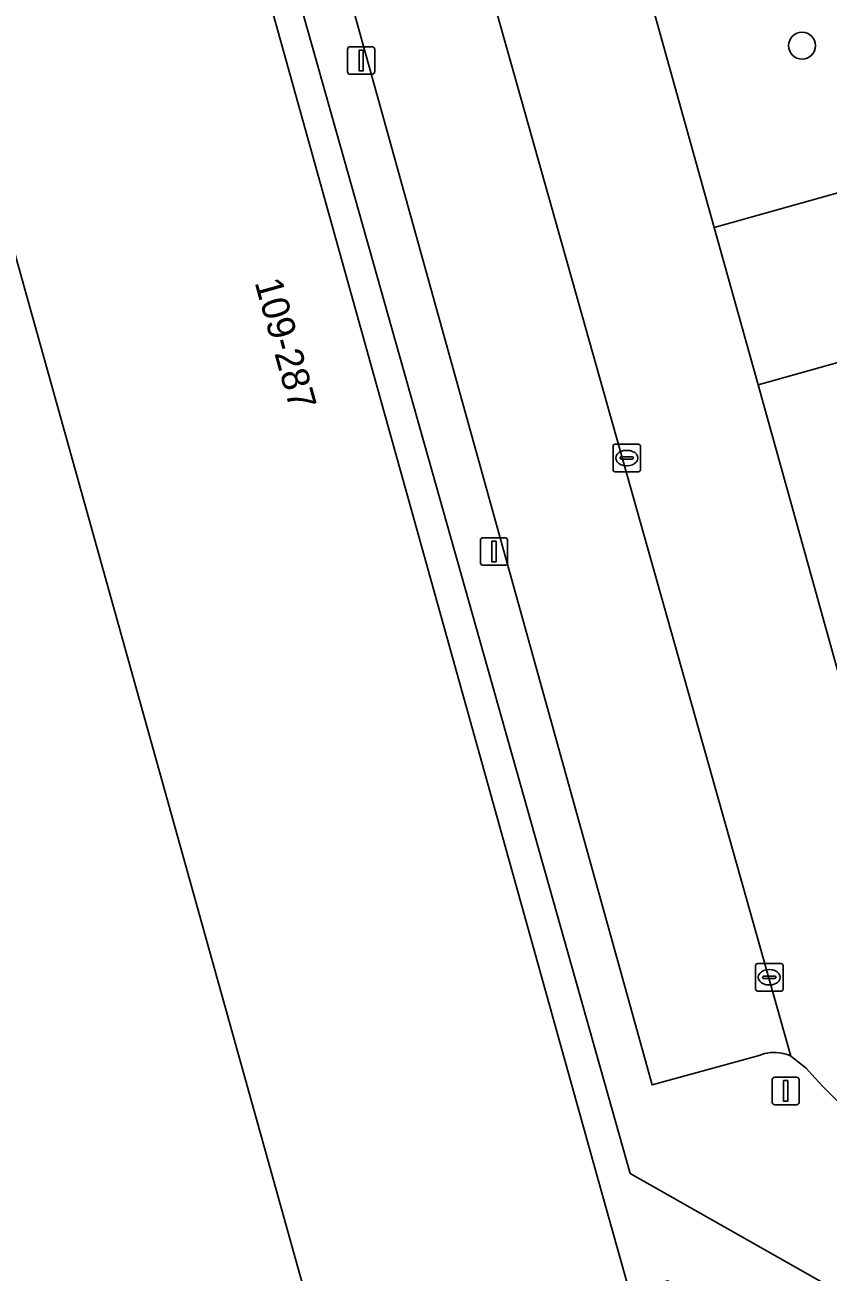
# Model space of a CAD drawing. Extents: x 159680 to 160786, y 387323 to 388340.
# Drawn here: x 159790.84 to 159820.07, y 387875.53 to 387920.9 of the extents above; entities that cross this region are included whole.
import ezdxf

# ---------------------------------------------------------------- set-up
doc = ezdxf.new("R2010")
doc.units = 0
for name, color, linetype in [('IMGEO_Boom', 7, 'Continuous'), ('IMGEO_Erf', 7, 'Continuous'), ('IMGEO_Kolk', 7, 'Continuous'), ('IMGEO_Lichtmast', 7, 'Continuous'), ('IMGEO_Pand', 7, 'Continuous'), ('IMGEO_Pand_nummerreeks', 7, 'Continuous'), ('IMGEO_Parkeervlak_open', 7, 'Continuous'), ('IMGEO_Rijbaan_lokaal_open', 7, 'Continuous'), ('IMGEO_Voetpad_open', 7, 'Continuous')]:
    doc.layers.add(name, color=color, linetype=linetype)

msp = doc.modelspace()

# ---------------------------------------------------------------- linework, layer by layer
at = {"layer": 'IMGEO_Boom'}
msp.add_circle((159819.119, 387920.147), 0.489, dxfattribs=at)
at = {"layer": 'IMGEO_Erf'}
msp.add_lwpolyline([(159855.695, 387800.602), (159856.484, 387800.91), (159853.031, 387810.594), (159849.48, 387809.209), (159834.729, 387847.038), (159833.556, 387846.581), (159832.044, 387847.281), (159828.131, 387857.251), (159823.313, 387869.646), (159817.654, 387873.188), (159815.606, 387870.293), (159814.209, 387869.903), (159816.632, 387861.214), (159809.352, 387859.172), (159805.677, 387858.141), (159779.046, 387953.498)], dxfattribs=at)
at = {"layer": 'IMGEO_Kolk'}
for p, q in [((159812.24, 387904.716), (159812.24, 387905.568)), ((159812.315, 387905.642), (159813.167, 387905.642)), ((159812.728, 387905.422), (159812.753, 387905.422)), ((159813.241, 387905.568), (159813.241, 387904.716)), ((159812.499, 387905.136), (159812.499, 387905.148)), ((159812.937, 387905.099), (159812.539, 387905.099)), ((159812.542, 387905.185), (159812.94, 387905.185)), ((159812.983, 387905.148), (159812.983, 387905.136)), ((159813.167, 387904.642), (159812.315, 387904.642)), ((159812.751, 387904.862), (159812.726, 387904.862)), ((159817.426, 387885.825), (159817.426, 387886.677)), ((159817.501, 387886.751), (159818.353, 387886.751)), ((159817.914, 387886.531), (159817.939, 387886.531)), ((159818.427, 387886.677), (159818.427, 387885.825)), ((159817.685, 387886.245), (159817.685, 387886.257)), ((159818.123, 387886.208), (159817.725, 387886.208)), ((159817.728, 387886.294), (159818.126, 387886.294)), ((159817.937, 387885.971), (159817.912, 387885.971)), ((159818.169, 387886.257), (159818.169, 387886.245)), ((159818.353, 387885.751), (159817.501, 387885.751))]:
    msp.add_line(p, q, dxfattribs=at)
for points in [[(159812.24, 387904.716), (159812.24, 387905.568)], [(159812.315, 387905.642), (159813.167, 387905.642)], [(159813.241, 387905.568), (159813.241, 387904.716)], [(159813.167, 387904.642), (159812.315, 387904.642)], [(159817.426, 387885.825), (159817.426, 387886.677)], [(159817.501, 387886.751), (159818.353, 387886.751)], [(159818.427, 387886.677), (159818.427, 387885.825)], [(159818.353, 387885.751), (159817.501, 387885.751)]]:
    msp.add_lwpolyline(points, dxfattribs=at)
for centre, radius, start, end in [((159812.317, 387905.566), 0.0765, 91.552, 178.448), ((159812.317, 387905.566), 0.0765, 91.552, 178.448), ((159813.165, 387905.566), 0.0765, 1.552, 88.448), ((159813.165, 387905.566), 0.0765, 1.552, 88.448), ((159812.539, 387905.145), 0.0403, 85.8775, 175.7526), ((159812.536, 387905.135), 0.0366, 178.938, 274.7102), ((159812.94, 387905.142), 0.043, 264.8664, 352.4533), ((159812.944, 387905.147), 0.0386, 1.7309, 96.639), ((159812.317, 387904.718), 0.0765, 181.552, 268.448), ((159812.317, 387904.718), 0.0765, 181.552, 268.448), ((159813.165, 387904.718), 0.0765, 271.552, 358.448), ((159813.165, 387904.718), 0.0765, 271.552, 358.448), ((159817.503, 387886.675), 0.0765, 91.552, 178.448), ((159817.503, 387886.675), 0.0765, 91.552, 178.448), ((159818.351, 387886.675), 0.0765, 1.552, 88.448), ((159818.351, 387886.675), 0.0765, 1.552, 88.448), ((159817.725, 387886.254), 0.0403, 85.8775, 175.7526), ((159817.722, 387886.244), 0.0366, 178.938, 274.7102), ((159818.126, 387886.251), 0.043, 264.8664, 352.4533), ((159818.13, 387886.256), 0.0386, 1.7309, 96.639), ((159817.503, 387885.827), 0.0765, 181.552, 268.448), ((159817.503, 387885.827), 0.0765, 181.552, 268.448), ((159818.351, 387885.827), 0.0765, 271.552, 358.448), ((159818.351, 387885.827), 0.0765, 271.552, 358.448)]:
    msp.add_arc(centre, radius, start, end, dxfattribs=at)
for centre, major_axis, ratio, start_param, end_param in [((159812.727, 387905.142), (-0.387, 0.002), 0.722429, 4.712389, 7.853982), ((159812.752, 387905.142), (-0.39, 0.002), 0.717154, 1.570796, 4.712389), ((159817.913, 387886.251), (-0.387, 0.002), 0.722429, 4.712389, 7.853982), ((159817.938, 387886.251), (-0.39, 0.002), 0.717154, 1.570796, 4.712389)]:
    msp.add_ellipse(centre, major_axis=major_axis, ratio=ratio, start_param=start_param, end_param=end_param, dxfattribs=at)
at = {"layer": 'IMGEO_Lichtmast'}
for p, q in [((159802.579, 387919.208), (159802.579, 387920.008)), ((159802.579, 387920.008), (159802.579, 387919.208)), ((159802.679, 387920.108), (159803.469, 387920.108)), ((159803.469, 387920.108), (159802.679, 387920.108)), ((159803.569, 387920.008), (159803.569, 387919.208)), ((159803.569, 387919.208), (159803.569, 387920.008)), ((159803.469, 387919.108), (159802.679, 387919.108)), ((159802.679, 387919.108), (159803.469, 387919.108)), ((159807.514, 387902.243), (159808.304, 387902.243)), ((159808.304, 387902.243), (159807.514, 387902.243)), ((159807.414, 387901.343), (159807.414, 387902.143)), ((159807.414, 387902.143), (159807.414, 387901.343)), ((159808.404, 387902.143), (159808.404, 387901.343)), ((159808.404, 387901.343), (159808.404, 387902.143)), ((159808.304, 387901.243), (159807.514, 387901.243)), ((159807.514, 387901.243), (159808.304, 387901.243)), ((159818.026, 387881.714), (159818.026, 387882.514)), ((159818.026, 387882.514), (159818.026, 387881.714)), ((159818.126, 387882.614), (159818.916, 387882.614)), ((159818.916, 387882.614), (159818.126, 387882.614)), ((159819.016, 387882.514), (159819.016, 387881.714)), ((159819.016, 387881.714), (159819.016, 387882.514)), ((159818.916, 387881.614), (159818.126, 387881.614)), ((159818.126, 387881.614), (159818.916, 387881.614))]:
    msp.add_line(p, q, dxfattribs=at)
for points in [[(159802.999, 387919.983), (159803.149, 387919.983), (159803.149, 387919.233), (159802.999, 387919.233), (159802.999, 387919.983)], [(159807.834, 387902.118), (159807.984, 387902.118), (159807.984, 387901.368), (159807.834, 387901.368), (159807.834, 387902.118)], [(159818.446, 387882.489), (159818.596, 387882.489), (159818.596, 387881.739), (159818.446, 387881.739), (159818.446, 387882.489)]]:
    msp.add_lwpolyline(points, dxfattribs=at)
for centre, start, end in [((159802.679, 387920.008), 90, 180), ((159802.679, 387920.008), 90, 180), ((159803.469, 387920.008), 0, 90), ((159803.469, 387920.008), 360, 90), ((159802.679, 387919.208), 180, 270), ((159802.679, 387919.208), 180, 270), ((159803.469, 387919.208), 270, 0), ((159803.469, 387919.208), 270, 0), ((159807.514, 387902.143), 90, 180), ((159807.514, 387902.143), 90, 180), ((159808.304, 387902.143), 0, 90), ((159808.304, 387902.143), 360, 90), ((159807.514, 387901.343), 180, 270), ((159807.514, 387901.343), 180, 270), ((159808.304, 387901.343), 270, 0), ((159808.304, 387901.343), 270, 0), ((159818.126, 387882.514), 90, 180), ((159818.126, 387882.514), 90, 180), ((159818.916, 387882.514), 0, 90), ((159818.916, 387882.514), 360, 90), ((159818.126, 387881.714), 180, 270), ((159818.126, 387881.714), 180, 270), ((159818.916, 387881.714), 270, 0), ((159818.916, 387881.714), 270, 0)]:
    msp.add_arc(centre, 0.1, start, end, dxfattribs=at)
at = {"layer": 'IMGEO_Pand'}
msp.add_lwpolyline([(159793.873, 387948.22), (159792.476, 387947.83), (159790.044, 387956.547), (159779.046, 387953.498), (159805.677, 387858.141), (159809.352, 387859.172), (159816.632, 387861.214), (159814.209, 387869.903), (159815.606, 387870.293), (159817.654, 387873.188), (159814.236, 387875.206), (159812.839, 387874.816), (159811.729, 387878.794), (159794.957, 387938.93), (159793.845, 387942.918), (159795.243, 387943.308), (159796.937, 387946.428)], close=True, dxfattribs=at)
at = {"layer": 'IMGEO_Parkeervlak_open'}
for points in [[(159801.092, 387939.006), (159798.147, 387938.168), (159813.659, 387882.338), (159817.555, 387883.408)], [(159818.713, 387883.386), (159807.156, 387924.411)]]:
    msp.add_lwpolyline(points, dxfattribs=at)
for points in [[(159834.725, 387930.348), (159812.935, 387924.236), (159815.922, 387913.529), (159837.727, 387919.646)], [(159839.332, 387913.925), (159817.518, 387907.806), (159820.522, 387897.036), (159842.352, 387903.159)]]:
    msp.add_lwpolyline(points, close=True, dxfattribs=at)
for centre, radius, start, end in [((159818.11, 387882.027), 1.489, 79.2283, 111.8795), ((159818.118, 387882.073), 1.442, 65.6247, 79.206)]:
    msp.add_arc(centre, radius, start, end, dxfattribs=at)
at = {"layer": 'IMGEO_Rijbaan_lokaal_open'}
for points in [[(159805.793, 387951.397), (159799.939, 387949.715), (159802.277, 387941.509), (159802.383, 387941.169), (159807.156, 387924.411), (159818.713, 387883.386), (159819.274, 387882.94)], [(159822.655, 387889.398), (159822.397, 387890.314), (159820.522, 387897.036), (159817.518, 387907.806), (159815.922, 387913.529), (159812.935, 387924.236), (159811.326, 387930.006), (159808.337, 387940.72)]]:
    msp.add_lwpolyline(points, dxfattribs=at)
msp.add_lwpolyline([(159839.332, 387913.925), (159837.727, 387919.646), (159815.922, 387913.529), (159817.518, 387907.806)], close=True, dxfattribs=at)
msp.add_arc((159828.255, 387890.353), 11.645, 219.5382, 290.7998, dxfattribs=at)
at = {"layer": 'IMGEO_Voetpad_open'}
for points in [[(159838.664, 387874.23), (159837.725, 387877.749), (159822.604, 387873.593), (159812.869, 387879.112), (159795.919, 387939.198), (159796.181, 387939.271), (159799.354, 387945.014), (159797.453, 387951.445), (159796.965, 387953.096), (159795.499, 387958.055), (159790.044, 387956.547), (159792.476, 387947.83), (159793.873, 387948.22), (159796.937, 387946.428), (159795.243, 387943.308), (159793.845, 387942.918), (159794.957, 387938.93), (159811.729, 387878.794), (159812.839, 387874.816)], [(159790.044, 387956.547), (159795.499, 387958.055), (159796.965, 387953.096), (159798.586, 387953.509), (159799.011, 387951.842), (159797.453, 387951.445), (159799.354, 387945.014), (159796.181, 387939.271), (159795.919, 387939.198), (159812.869, 387879.112), (159822.604, 387873.593), (159837.725, 387877.749), (159841.744, 387878.794), (159847.208, 387880.408)], [(159817.555, 387883.408), (159813.659, 387882.338), (159798.147, 387938.168), (159801.092, 387939.006)], [(159819.274, 387882.94), (159818.713, 387883.386)]]:
    msp.add_lwpolyline(points, dxfattribs=at)
for centre, radius, start, end in [((159818.11, 387882.027), 1.489, 79.2283, 111.8795), ((159818.118, 387882.073), 1.442, 65.6247, 79.206), ((159828.255, 387890.353), 11.645, 219.5382, 290.7998)]:
    msp.add_arc(centre, radius, start, end, dxfattribs=at)

# ---------------------------------------------------------------- texts
at = {"layer": 'IMGEO_Pand_nummerreeks'}
msp.add_text('109-287', height=1, rotation=285.5841, dxfattribs=at).set_placement((159799.192, 387911.539))

doc.saveas('drawing.dxf')
